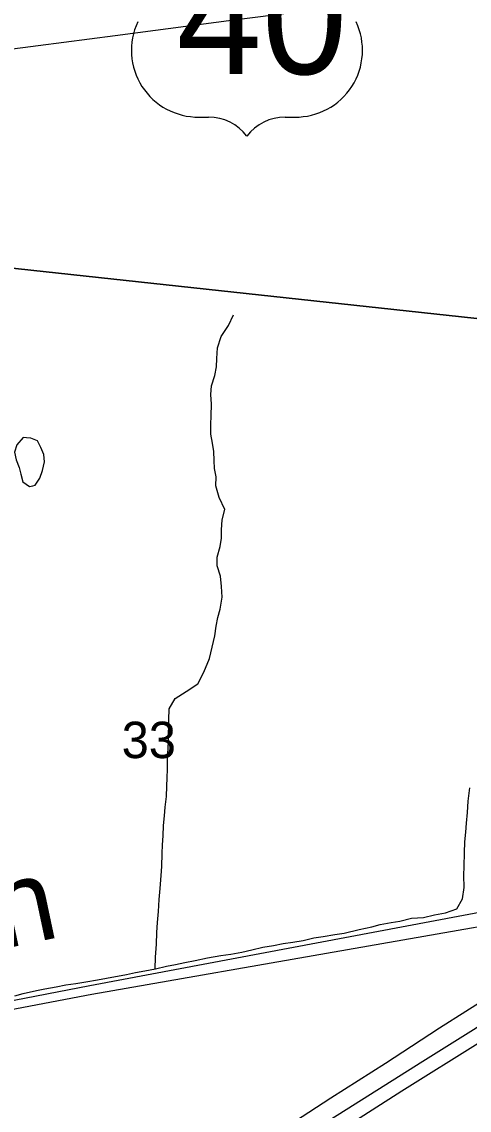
# Model space of a CAD drawing. Extents: x 831 to 1552, y 430 to 870.
# Drawn here: x 1333.77 to 1344.04, y 702.9 to 727.92 of the extents above; entities that cross this region are included whole.
import ezdxf

# ---------------------------------------------------------------- set-up
doc = ezdxf.new("R2010")
doc.units = 0
for name, color, linetype in [('GM_X_Corporation', 7, 'Continuous'), ('GM_X_County_Road', 7, 'Continuous'), ('GM_X_Minor_Lake', 7, 'Continuous'), ('GM_X_Minor_River', 7, 'Continuous'), ('GM_X_Minor_River_Text', 7, 'Continuous'), ('GM_X_Rail_Line', 7, 'Continuous'), ('GM_X_Section_Text', 7, 'Continuous'), ('GM_X_State_Route', 7, 'Continuous'), ('GM_X_US_Location', 7, 'Continuous'), ('GM_X_US_Route', 7, 'Continuous'), ('GM_X_US_Shield', 7, 'Continuous')]:
    doc.layers.add(name, color=color, linetype=linetype)

msp = doc.modelspace()

# ---------------------------------------------------------------- linework, layer by layer
at = {"layer": 'GM_X_Corporation'}
for points in [[(1329.567, 743.48), (1348.747, 741.721), (1347.89, 720.702), (1327.468, 722.912)], [(1327.468, 722.912), (1347.89, 720.702), (1346.049, 700.645), (1325.539, 702.531)]]:
    msp.add_lwpolyline(points, close=True, dxfattribs=at)
at = {"layer": 'GM_X_County_Road'}
msp.add_lwpolyline([(1340.029, 702.639), (1340.863, 703.18), (1342.12, 703.983), (1342.713, 704.369), (1343.362, 704.795), (1344.569, 705.559), (1345.509, 706.164), (1345.869, 706.407), (1346.224, 706.659), (1346.621, 706.957), (1346.863, 707.151), (1347.142, 707.396), (1347.599, 707.817), (1347.931, 708.141), (1349.418, 709.601), (1350.216, 710.385), (1350.462, 710.645)], dxfattribs=at)
at = {"layer": 'GM_X_Minor_Lake'}
for points in [[(1333.879, 718.358), (1333.797, 718.362), (1333.651, 718.197), (1333.603, 718.023), (1333.639, 717.847), (1333.705, 717.672), (1333.749, 717.519), (1333.792, 717.344), (1333.943, 717.236), (1334.02, 717.252)], [(1334.02, 717.252), (1334.072, 717.265), (1334.18, 717.431), (1334.243, 717.605), (1334.291, 717.802), (1334.271, 717.976), (1334.204, 718.137), (1334.13, 718.29), (1333.979, 718.352), (1333.879, 718.358)]]:
    msp.add_lwpolyline(points, dxfattribs=at)
at = {"layer": 'GM_X_Minor_River'}
for points in [[(1336.829, 706.149), (1336.84, 706.416), (1336.859, 706.712), (1336.87, 706.985), (1336.888, 707.213), (1336.906, 707.463), (1336.925, 707.744), (1336.943, 707.994), (1336.97, 708.298), (1336.98, 708.503), (1336.991, 708.799), (1337.001, 708.996), (1337.011, 709.209), (1337.022, 709.444), (1337.047, 709.664), (1337.057, 709.869), (1337.091, 710.112), (1337.101, 710.347), (1337.104, 710.537), (1337.114, 710.742), (1337.117, 711.015), (1337.127, 711.205), (1337.137, 711.402), (1337.143, 711.873), (1337.154, 712.124), (1337.286, 712.365), (1337.546, 712.521), (1337.807, 712.7), (1337.947, 712.972), (1338.08, 713.282), (1338.136, 713.547), (1338.2, 713.805), (1338.233, 714.024), (1338.266, 714.222), (1338.322, 714.418), (1338.371, 714.691), (1338.351, 714.942), (1338.331, 715.178), (1338.258, 715.414), (1338.253, 715.612), (1338.324, 715.854), (1338.357, 716.051), (1338.352, 716.241), (1338.37, 716.469), (1338.434, 716.711), (1338.3, 716.986), (1338.22, 717.253), (1338.23, 717.458), (1338.194, 717.648), (1338.182, 717.838), (1338.177, 718.043), (1338.149, 718.233), (1338.105, 718.439), (1338.108, 718.659), (1338.118, 718.864), (1338.122, 719.13), (1338.109, 719.35), (1338.127, 719.548), (1338.198, 719.79), (1338.239, 719.987), (1338.249, 720.177), (1338.259, 720.427), (1338.346, 720.685), (1338.516, 720.941), (1338.633, 721.182)], [(1334.301, 705.687), (1334.56, 705.737), (1334.781, 705.78), (1335.009, 705.815), (1335.238, 705.851), (1335.504, 705.893), (1335.717, 705.936), (1336.174, 706.022), (1336.38, 706.065), (1336.593, 706.1), (1336.837, 706.15), (1337.088, 706.208), (1337.294, 706.251), (1337.515, 706.294), (1337.751, 706.344), (1338.033, 706.402), (1338.337, 706.459), (1338.566, 706.486), (1338.824, 706.529), (1339.053, 706.587), (1339.304, 706.644), (1339.548, 706.687), (1339.769, 706.73), (1339.99, 706.765), (1340.226, 706.801), (1340.477, 706.858), (1340.69, 706.894), (1340.957, 706.936), (1341.17, 706.971), (1341.513, 707.051), (1341.802, 707.116), (1341.993, 707.167), (1342.252, 707.217), (1342.449, 707.245), (1342.716, 707.31), (1342.99, 707.329), (1343.241, 707.387), (1343.5, 707.437), (1343.76, 707.525), (1343.884, 707.759), (1343.925, 708.017), (1343.921, 708.298), (1343.924, 708.511), (1343.935, 708.814), (1343.938, 709.065), (1343.964, 709.292), (1343.981, 709.497), (1344, 709.74), (1344.018, 710.006), (1344.052, 710.309)], [(1333.608, 705.529), (1333.799, 705.579), (1334.103, 705.652), (1334.301, 705.687)]]:
    msp.add_lwpolyline(points, dxfattribs=at)
at = {"layer": 'GM_X_Rail_Line'}
for points in [[(1347.068, 707.913), (1345.209, 707.623), (1335.331, 705.755), (1325.651, 703.882), (1316.479, 702.146), (1309.906, 700.809), (1302.408, 699.333), (1299.88, 698.86), (1298.165, 698.538), (1295.52, 698.073)], [(1250.766, 679.957), (1255.444, 683.813), (1257.495, 685.358), (1259.895, 687.02), (1261.608, 688.118), (1265.466, 690.461), (1268.571, 692.318), (1270.198, 693.26), (1277.176, 696.209), (1284.864, 698.305), (1290.582, 698.552), (1291.934, 698.299), (1293.404, 698.016), (1295.482, 697.897), (1297.508, 698.271), (1299.512, 698.644), (1302.371, 699.157), (1309.027, 700.546), (1335.38, 705.567), (1347.114, 707.619), (1348.184, 707.837)]]:
    msp.add_lwpolyline(points, dxfattribs=at)
at = {"layer": 'GM_X_State_Route'}
for points in [[(1333.187, 697.843), (1335.988, 699.621), (1336.934, 700.218), (1339.247, 701.676), (1342.98, 704.025), (1344.137, 704.754), (1345.24, 705.451), (1347.026, 706.576), (1348.077, 707.238), (1349.128, 707.902), (1350.076, 708.496), (1351.915, 709.656), (1352.545, 710.051), (1352.915, 710.283), (1353.297, 710.524), (1353.703, 710.78), (1354.282, 711.144), (1356.61, 712.615), (1357.165, 712.965)], [(1327.572, 693.951), (1327.781, 694.084), (1329.474, 695.148), (1330.997, 696.104), (1332.731, 697.181), (1334.273, 698.15), (1336.026, 699.258), (1337.813, 700.381), (1339.619, 701.524), (1340.853, 702.296), (1342.496, 703.341), (1344.305, 704.48), (1346.259, 705.713), (1348.062, 706.849), (1349.964, 708.043), (1351.69, 709.137), (1352.765, 709.811)]]:
    msp.add_lwpolyline(points, dxfattribs=at)
at = {"layer": 'GM_X_US_Route'}
msp.add_lwpolyline([(1327.897, 726.561), (1329.462, 726.76), (1330.817, 726.937), (1331.679, 727.052), (1332.603, 727.174), (1334.144, 727.374), (1335.915, 727.605), (1336.839, 727.726), (1338.525, 727.95), (1339.611, 728.089), (1340.596, 728.22), (1342.438, 728.463), (1342.506, 728.472), (1343.368, 728.587), (1345.154, 728.821), (1346.632, 729.017), (1347.232, 729.097), (1347.679, 729.157), (1348.231, 729.233)], dxfattribs=at)
at = {"layer": 'GM_X_US_Shield'}
for p, q in [((1337.839, 725.729), (1338.058, 725.729)), ((1339.816, 725.729), (1340.036, 725.729))]:
    msp.add_line(p, q, dxfattribs=at)
for centre, radius, start, end in [((1337.822, 727.267), 1.538, 154.8319, 270.6383), ((1340.053, 727.267), 1.538, 269.3617, 25.1681), ((1338.058, 724.63), 1.099, 36.8699, 90), ((1339.816, 724.63), 1.099, 90, 143.1301)]:
    msp.add_arc(centre, radius, start, end, dxfattribs=at)

# ---------------------------------------------------------------- texts
at = {"layer": 'GM_X_Minor_River_Text'}
msp.add_text('Ditch', height=1.8938, rotation=11.9823, dxfattribs=at).set_placement((1329.037, 705.69))
at = {"layer": 'GM_X_Section_Text'}
msp.add_text('33', height=0.8371, rotation=0, dxfattribs=at).set_placement((1336.062, 710.993))
at = {"layer": 'GM_X_US_Location'}
msp.add_text('40', height=0.00379, rotation=0, dxfattribs=at).set_placement((1338.154, 727.231))
at = {"layer": 'GM_X_US_Shield'}
msp.add_text('40', height=2.6367, dxfattribs=at).set_placement((1337.319, 726.717))

doc.saveas('drawing.dxf')
